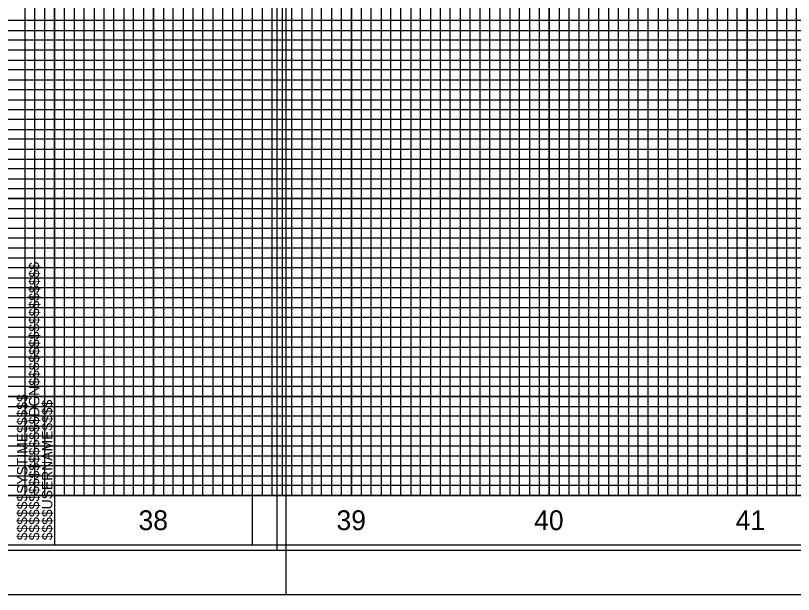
# Model space of a CAD drawing. Extents: x 2345490 to 2436403, y 465165 to 573888.
# Drawn here: x 2384497.1 to 2384890.2, y 500557.8 to 500850.3 of the extents above; entities that cross this region are included whole.
import ezdxf

# ---------------------------------------------------------------- set-up
doc = ezdxf.new("R2010")
doc.units = 0
for name, color, linetype in [('Exist Vertical Profile Horizontal Axis Label Major', 7, 'Continuous'), ('Old_Level_18', 7, 'Continuous'), ('Old_Level_40', 7, 'Continuous'), ('Old_Level_41', 7, 'Continuous'), ('Old_Level_42', 7, 'Continuous'), ('Old_Level_43', 7, 'Continuous'), ('Old_Level_50', 7, 'Continuous'), ('Old_Level_51', 7, 'Continuous'), ('Old_Level_57', 7, 'Continuous'), ('Old_Level_63', 7, 'Continuous')]:
    doc.layers.add(name, color=color, linetype=linetype)

msp = doc.modelspace()

# ---------------------------------------------------------------- linework, layer by layer
at = {"layer": 'Old_Level_18'}
msp.add_line((2384516.79875, 500582.775), (2384516.79875, 500582.775), dxfattribs=at)
msp.add_line((2384516.79875, 500582.775), (2384516.79875, 500582.775), dxfattribs=at)
for points in [[(2384616.79875, 501632.775), (2383116.79875, 501632.775), (2383116.79875, 500582.775), (2384616.79875, 500582.775)], [(2386016.79875, 501632.775), (2384516.79875, 501632.775), (2384516.79875, 500582.775), (2386016.79875, 500582.775)]]:
    msp.add_lwpolyline(points, close=True, dxfattribs=at)
at = {"layer": 'Old_Level_40'}
msp.add_line((2384516.79875, 500582.775), (2384516.79875, 500582.775), dxfattribs=at)
msp.add_line((2384516.79875, 500582.775), (2384516.79875, 500582.775), dxfattribs=at)
msp.add_line((2384516.79875, 500582.775), (2384516.79875, 500582.775), dxfattribs=at)
msp.add_line((2384516.79875, 500582.775), (2384516.79875, 500582.775), dxfattribs=at)
at = {"layer": 'Old_Level_41'}
for p, q in [((2384616.79875, 500607.775), (2383116.79875, 500607.775)), ((2386016.79875, 500607.775), (2384516.79875, 500607.775))]:
    msp.add_line(p, q, dxfattribs=at)
for points in [[(2384516.79875, 501632.775), (2384566.79875, 501632.775), (2384566.79875, 500607.775), (2384616.79875, 500607.775), (2384616.79875, 501632.775), (2384666.79875, 501632.775), (2384666.79875, 500607.775), (2384716.79875, 500607.775), (2384716.79875, 501632.775), (2384766.79875, 501632.775), (2384766.79875, 500607.775), (2384816.79875, 500607.775), (2384816.79875, 501632.775), (2384866.79875, 501632.775), (2384866.79875, 500607.775), (2384916.79875, 500607.775), (2384916.79875, 501632.775), (2384966.79875, 501632.775), (2384966.79875, 500607.775), (2385016.79875, 500607.775), (2385016.79875, 501632.775), (2385066.79875, 501632.775), (2385066.79875, 500607.775), (2385116.79875, 500607.775)], [(2384591.79875, 500607.775), (2384591.79875, 501632.775), (2384641.79875, 501632.775), (2384641.79875, 500607.775), (2384691.79875, 500607.775), (2384691.79875, 501632.775), (2384741.79875, 501632.775), (2384741.79875, 500607.775), (2384791.79875, 500607.775), (2384791.79875, 501632.775), (2384841.79875, 501632.775), (2384841.79875, 500607.775), (2384891.79875, 500607.775), (2384891.79875, 501632.775), (2384941.79875, 501632.775), (2384941.79875, 500607.775), (2384991.79875, 500607.775), (2384991.79875, 501632.775), (2385041.79875, 501632.775), (2385041.79875, 500607.775), (2385091.79875, 500607.775), (2385091.79875, 501632.775), (2385141.79875, 501632.775)], [(2384541.79875, 501495.225), (2384541.79875, 500607.775)], [(2384616.79875, 500832.775), (2383116.79875, 500832.775), (2383116.79875, 500782.775), (2384616.79875, 500782.775)], [(2386016.79875, 500832.775), (2384516.79875, 500832.775), (2384516.79875, 500782.775), (2386016.79875, 500782.775)], [(2384616.79875, 500732.775), (2383116.79875, 500732.775), (2383116.79875, 500682.775), (2384616.79875, 500682.775)], [(2386016.79875, 500732.775), (2384516.79875, 500732.775), (2384516.79875, 500682.775), (2386016.79875, 500682.775)], [(2384616.79875, 500657.775), (2383116.79875, 500657.775), (2383116.79875, 500707.775), (2384616.79875, 500707.775)], [(2386016.79875, 500657.775), (2384516.79875, 500657.775), (2384516.79875, 500707.775), (2386016.79875, 500707.775)], [(2384616.79875, 500632.775), (2383116.79875, 500632.775)], [(2386016.79875, 500632.775), (2384516.79875, 500632.775)], [(2384554.29875, 500582.775), (2384554.29875, 500582.775)]]:
    msp.add_lwpolyline(points, dxfattribs=at)
at = {"layer": 'Old_Level_42'}
for points in [[(2384466.79875, 501495.225), (2384466.79875, 500607.775), (2384516.79875, 500607.775), (2384516.79875, 501495.225)], [(2384566.79875, 501495.225), (2384566.79875, 500607.775), (2384616.79875, 500607.775)], [(2384616.79875, 500757.775), (2383116.79875, 500757.775), (2383116.79875, 500807.775), (2384616.79875, 500807.775)], [(2386016.79875, 500757.775), (2384516.79875, 500757.775), (2384516.79875, 500807.775), (2386016.79875, 500807.775)]]:
    msp.add_lwpolyline(points, dxfattribs=at)
at = {"layer": 'Old_Level_43'}
for points in [[(2384571.79875, 501632.775), (2384571.79875, 500607.775), (2384576.79875, 500607.775), (2384576.79875, 501632.775)], [(2384581.79875, 501632.775), (2384581.79875, 500607.775), (2384586.79875, 500607.775), (2384586.79875, 501632.775)], [(2384596.79875, 501632.775), (2384596.79875, 500607.775), (2384601.79875, 500607.775), (2384601.79875, 501632.775)], [(2384606.79875, 501632.775), (2384606.79875, 500607.775), (2384611.79875, 500607.775), (2384611.79875, 501632.775)], [(2384621.79875, 501632.775), (2384621.79875, 500607.775), (2384626.79875, 500607.775), (2384626.79875, 501632.775)], [(2384631.79875, 501632.775), (2384631.79875, 500607.775), (2384636.79875, 500607.775), (2384636.79875, 501632.775)], [(2384646.79875, 501632.775), (2384646.79875, 500607.775), (2384651.79875, 500607.775), (2384651.79875, 501632.775)], [(2384656.79875, 501632.775), (2384656.79875, 500607.775), (2384661.79875, 500607.775), (2384661.79875, 501632.775)], [(2384671.79875, 501632.775), (2384671.79875, 500607.775), (2384676.79875, 500607.775), (2384676.79875, 501632.775)], [(2384681.79875, 501632.775), (2384681.79875, 500607.775), (2384686.79875, 500607.775), (2384686.79875, 501632.775)], [(2384696.79875, 501632.775), (2384696.79875, 500607.775), (2384701.79875, 500607.775), (2384701.79875, 501632.775)], [(2384706.79875, 501632.775), (2384706.79875, 500607.775), (2384711.79875, 500607.775), (2384711.79875, 501632.775)], [(2384721.79875, 501632.775), (2384721.79875, 500607.775), (2384726.79875, 500607.775), (2384726.79875, 501632.775)], [(2384731.79875, 500607.775), (2384736.79875, 500607.775), (2384736.79875, 501632.775)], [(2384731.79875, 501632.775), (2384731.79875, 500607.775)], [(2384746.79875, 501632.775), (2384746.79875, 500607.775), (2384751.79875, 500607.775), (2384751.79875, 501632.775)], [(2384756.79875, 501632.775), (2384756.79875, 500607.775), (2384761.79875, 500607.775), (2384761.79875, 501632.775)], [(2384771.79875, 501632.775), (2384771.79875, 500607.775), (2384776.79875, 500607.775), (2384776.79875, 501632.775)], [(2384781.79875, 501632.775), (2384781.79875, 500607.775), (2384786.79875, 500607.775), (2384786.79875, 501632.775)], [(2384796.79875, 501632.775), (2384796.79875, 500607.775), (2384801.79875, 500607.775), (2384801.79875, 501632.775)], [(2384806.79875, 501632.775), (2384806.79875, 500607.775), (2384811.79875, 500607.775), (2384811.79875, 501632.775)], [(2384821.79875, 501632.775), (2384821.79875, 500607.775), (2384826.79875, 500607.775), (2384826.79875, 501632.775)], [(2384831.79875, 501632.775), (2384831.79875, 500607.775), (2384836.79875, 500607.775), (2384836.79875, 501632.775)], [(2384846.79875, 501632.775), (2384846.79875, 500607.775), (2384851.79875, 500607.775), (2384851.79875, 501632.775)], [(2384856.79875, 501632.775), (2384856.79875, 500607.775), (2384861.79875, 500607.775), (2384861.79875, 501632.775)], [(2384871.79875, 501632.775), (2384871.79875, 500607.775), (2384876.79875, 500607.775), (2384876.79875, 501632.775)], [(2384881.79875, 501632.775), (2384881.79875, 500607.775), (2384886.79875, 500607.775), (2384886.79875, 501632.775)], [(2384501.79875, 501495.225), (2384501.79875, 500607.775)], [(2384501.79875, 500607.775), (2384506.79875, 500607.775), (2384506.79875, 501495.225)], [(2384511.79875, 501495.225), (2384511.79875, 500607.775), (2384521.79875, 500607.775), (2384521.79875, 501495.225)], [(2384526.79875, 501495.225), (2384526.79875, 500607.775), (2384531.79875, 500607.775), (2384531.79875, 501495.225)], [(2384536.79875, 501495.225), (2384536.79875, 500607.775), (2384546.79875, 500607.775), (2384546.79875, 501495.225)], [(2384551.79875, 501495.225), (2384551.79875, 500607.775), (2384556.79875, 500607.775), (2384556.79875, 501495.225)], [(2384561.79875, 501495.225), (2384561.79875, 500607.775), (2384571.79875, 500607.775)], [(2384566.79875, 500847.775), (2383166.79875, 500847.775), (2383166.79875, 500842.775), (2384566.79875, 500842.775)], [(2385966.79875, 500847.775), (2384566.79875, 500847.775), (2384566.79875, 500842.775), (2385966.79875, 500842.775)], [(2384566.79875, 500837.775), (2383166.79875, 500837.775), (2383166.79875, 500827.775), (2384566.79875, 500827.775)], [(2385966.79875, 500837.775), (2384566.79875, 500837.775), (2384566.79875, 500827.775), (2385966.79875, 500827.775)], [(2384566.79875, 500822.775), (2383166.79875, 500822.775), (2383166.79875, 500817.775), (2384566.79875, 500817.775)], [(2385966.79875, 500822.775), (2384566.79875, 500822.775), (2384566.79875, 500817.775), (2385966.79875, 500817.775)], [(2384566.79875, 500812.775), (2383166.79875, 500812.775)], [(2385966.79875, 500812.775), (2384566.79875, 500812.775)], [(2383166.79875, 500802.775), (2384566.79875, 500802.775)], [(2384566.79875, 500802.775), (2385966.79875, 500802.775)], [(2384566.79875, 500797.775), (2383166.79875, 500797.775), (2383166.79875, 500792.775), (2384566.79875, 500792.775)], [(2385966.79875, 500797.775), (2384566.79875, 500797.775), (2384566.79875, 500792.775), (2385966.79875, 500792.775)], [(2384566.79875, 500787.775), (2383166.79875, 500787.775)], [(2385966.79875, 500787.775), (2384566.79875, 500787.775)], [(2383166.79875, 500777.775), (2384566.79875, 500777.775)], [(2384566.79875, 500777.775), (2385966.79875, 500777.775)], [(2384566.79875, 500772.775), (2383166.79875, 500772.775), (2383166.79875, 500767.775), (2384566.79875, 500767.775)], [(2385966.79875, 500772.775), (2384566.79875, 500772.775), (2384566.79875, 500767.775), (2385966.79875, 500767.775)], [(2384566.79875, 500762.775), (2383166.79875, 500762.775), (2383166.79875, 500752.775), (2384566.79875, 500752.775)], [(2385966.79875, 500762.775), (2384566.79875, 500762.775), (2384566.79875, 500752.775), (2385966.79875, 500752.775)], [(2384566.79875, 500747.775), (2383166.79875, 500747.775), (2383166.79875, 500742.775), (2384566.79875, 500742.775)], [(2385966.79875, 500747.775), (2384566.79875, 500747.775), (2384566.79875, 500742.775), (2385966.79875, 500742.775)], [(2384566.79875, 500737.775), (2383166.79875, 500737.775), (2383166.79875, 500727.775), (2384566.79875, 500727.775)], [(2385966.79875, 500737.775), (2384566.79875, 500737.775), (2384566.79875, 500727.775), (2385966.79875, 500727.775)], [(2384566.79875, 500722.775), (2383166.79875, 500722.775), (2383166.79875, 500717.775), (2384566.79875, 500717.775)], [(2385966.79875, 500722.775), (2384566.79875, 500722.775), (2384566.79875, 500717.775), (2385966.79875, 500717.775)], [(2384566.79875, 500712.775), (2383166.79875, 500712.775), (2383166.79875, 500702.775), (2384566.79875, 500702.775)], [(2385966.79875, 500712.775), (2384566.79875, 500712.775), (2384566.79875, 500702.775), (2385966.79875, 500702.775)], [(2384566.79875, 500697.775), (2383166.79875, 500697.775), (2383166.79875, 500692.775), (2384566.79875, 500692.775)], [(2385966.79875, 500697.775), (2384566.79875, 500697.775), (2384566.79875, 500692.775), (2385966.79875, 500692.775)], [(2384566.79875, 500687.775), (2383166.79875, 500687.775), (2383166.79875, 500677.775), (2384566.79875, 500677.775)], [(2385966.79875, 500687.775), (2384566.79875, 500687.775), (2384566.79875, 500677.775), (2385966.79875, 500677.775)], [(2384566.79875, 500672.775), (2383166.79875, 500672.775), (2383166.79875, 500667.775), (2384566.79875, 500667.775)], [(2385966.79875, 500672.775), (2384566.79875, 500672.775), (2384566.79875, 500667.775), (2385966.79875, 500667.775)], [(2384566.79875, 500662.775), (2383166.79875, 500662.775), (2383166.79875, 500652.775), (2384566.79875, 500652.775)], [(2385966.79875, 500662.775), (2384566.79875, 500662.775), (2384566.79875, 500652.775), (2385966.79875, 500652.775)], [(2384566.79875, 500647.775), (2383166.79875, 500647.775), (2383166.79875, 500642.775), (2384566.79875, 500642.775)], [(2385966.79875, 500647.775), (2384566.79875, 500647.775), (2384566.79875, 500642.775), (2385966.79875, 500642.775)], [(2384566.79875, 500637.775), (2383166.79875, 500637.775), (2383166.79875, 500627.775), (2384566.79875, 500627.775)], [(2385966.79875, 500637.775), (2384566.79875, 500637.775), (2384566.79875, 500627.775), (2385966.79875, 500627.775)], [(2384566.79875, 500622.775), (2383166.79875, 500622.775), (2383166.79875, 500617.775), (2384566.79875, 500617.775)], [(2385966.79875, 500622.775), (2384566.79875, 500622.775), (2384566.79875, 500617.775), (2385966.79875, 500617.775)], [(2384566.79875, 500612.775), (2383166.79875, 500612.775)], [(2385966.79875, 500612.775), (2384566.79875, 500612.775)]]:
    msp.add_lwpolyline(points, dxfattribs=at)
at = {"layer": 'Old_Level_50'}
for points in [[(2384629.29875, 501635.325), (2382962.79875, 501635.325), (2382962.79875, 500580.225), (2384629.29875, 500580.225)], [(2386029.29875, 501635.325), (2384362.79875, 501635.325), (2384362.79875, 500580.225), (2386029.29875, 500580.225)]]:
    msp.add_lwpolyline(points, close=True, dxfattribs=at)
at = {"layer": 'Old_Level_51'}
for points in [[(2384633.79875, 501657.775), (2382949.79875, 501657.775), (2382949.79875, 500557.775), (2384633.79875, 500557.775)], [(2386033.79875, 501657.775), (2384349.79875, 501657.775), (2384349.79875, 500557.775), (2386033.79875, 500557.775)]]:
    msp.add_lwpolyline(points, close=True, dxfattribs=at)
at = {"layer": 'Old_Level_57'}
for p, q in [((2384566.79875, 500607.77525), (2384566.79875, 501057.77525)), ((2384566.79875, 500607.87525), (2384566.79875, 501057.77525)), ((2384666.79875, 500607.77525), (2384666.79875, 501057.77525)), ((2384666.79875, 500607.87525), (2384666.79875, 501057.77525)), ((2384766.79875, 500607.77525), (2384766.79875, 501057.77525)), ((2384766.79875, 500607.87525), (2384766.79875, 501057.77525)), ((2384866.79875, 500607.77525), (2384866.79875, 501057.77525)), ((2384866.79875, 500607.87525), (2384866.79875, 501057.77525)), ((2381716.79925, 500807.77525), (2385066.79875, 500807.77525)), ((2381716.79925, 500757.77525), (2385066.79875, 500757.77525)), ((2381716.79925, 500707.77525), (2385066.79875, 500707.77525)), ((2381716.799, 500657.77525), (2385066.79875, 500657.77525)), ((2381716.79925, 500607.77525), (2385066.79875, 500607.77525))]:
    msp.add_line(p, q, dxfattribs=at)
at = {"layer": 'Old_Level_63'}
msp.add_line((2381766.79875, 500607.775), (2384797.7405, 500607.775), dxfattribs=at)

# ---------------------------------------------------------------- texts
at = {"layer": 'Exist Vertical Profile Horizontal Axis Label Major'}
for s, p in [('38', (2384559.26698, 500590.275)), ('39', (2384659.30941, 500590.275)), ('40', (2384759.18516, 500590.275)), ('41', (2384861.02456, 500590.275))]:
    msp.add_text(s, height=10, dxfattribs=at).set_placement(p)
at = {"layer": 'Old_Level_41'}
for s, p in [('$$$$$$$$$$$$$$$$DGN$$$$$$$$$$$$$$$$', (2384509.14875, 500585.1375)), ('$$$$$$SYSTIME$$$$$', (2384503.09875, 500585.1375)), ('$$$$USERNAME$$$$', (2384515.72375, 500585.15))]:
    msp.add_text(s, height=5.25, rotation=90, dxfattribs=at).set_placement(p)

doc.saveas('drawing.dxf')
